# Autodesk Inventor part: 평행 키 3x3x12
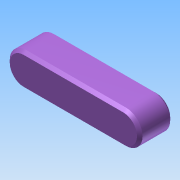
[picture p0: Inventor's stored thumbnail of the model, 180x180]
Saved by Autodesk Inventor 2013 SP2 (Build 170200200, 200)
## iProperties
Created: 2025-10
Part Number: 평행 키 3x3x12
Material: Generic
Document SubType Name: Modeling
Designer: 601
Density: 1 g/cm^3
Author: 601
변환 표준: STEP AP214IS
전처리기: Build: 200, Release: 2013 SP2 Update 6 - Date: Thu 07/17/2014
전송 단위: 밀리미터
불확실성: 0.01
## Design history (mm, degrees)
node "평행 키 3x3x121"
body "Solid1"
node "기준1"
